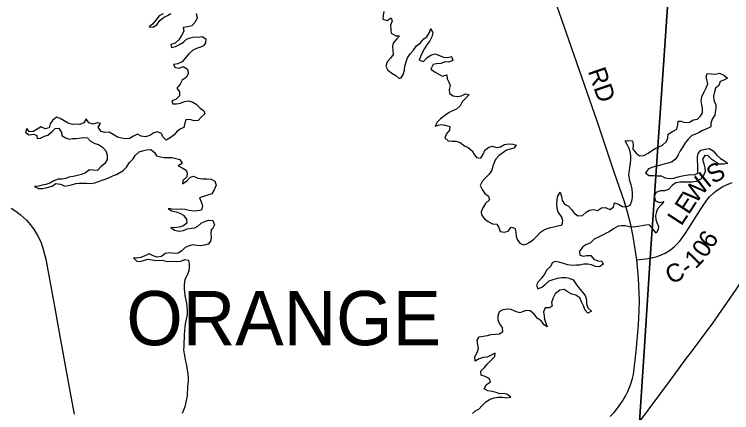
# Model space of a CAD drawing. Extents: x 1674899 to 2057726, y 653888 to 988278.
# Drawn here: x 1834248 to 1846138, y 797406 to 804014 of the extents above; entities that cross this region are included whole.
import ezdxf

# ---------------------------------------------------------------- set-up
doc = ezdxf.new("R2010")
doc.units = 0
for name, color, linetype in [('GM_X_County_Road', 7, 'Continuous'), ('GM_X_County_Road_Text', 7, 'Continuous'), ('GM_X_Interstate_Route', 7, 'Continuous'), ('GM_X_Major_Lake', 7, 'Continuous'), ('GM_X_Township', 7, 'Continuous'), ('GM_X_Township_Text', 7, 'Continuous'), ('SH_Data', 7, 'Continuous')]:
    doc.layers.add(name, color=color, linetype=linetype)

msp = doc.modelspace()

# ---------------------------------------------------------------- linework, layer by layer
at = {"layer": 'GM_X_County_Road'}
for points in [[(1844123, 797340), (1844188, 797408), (1844248, 797481), (1844329, 797598), (1844353, 797638), (1844376, 797680), (1844415, 797758), (1844451, 797843), (1844467, 797886), (1844494, 797974), (1844505, 798018), (1844519, 798085), (1844557, 798429), (1844595, 798866), (1844607, 799102), (1844608, 799265), (1844601, 799518), (1844595, 799631), (1844566, 799941), (1844505, 800330), (1844464, 800522), (1844412, 800732), (1844363, 800904), (1844193, 801395), (1843910, 802243), (1843360, 803811), (1842894, 805162)], [(1844838, 799981), (1844901, 799998), (1844968, 800023), (1845033, 800054), (1845064, 800071), (1845094, 800091), (1845124, 800110), (1845190, 800164), (1845278, 800253), (1845373, 800385), (1845425, 800462), (1845644, 800809), (1845729, 800932), (1845773, 800986), (1845847, 801059), (1845874, 801080), (1845931, 801120), (1845991, 801156), (1846052, 801187), (1846116, 801212), (1846148, 801222)], [(1834194, 800797), (1834287, 800738), (1834352, 800690), (1834449, 800601), (1834514, 800523), (1834576, 800442), (1834637, 800335), (1834686, 800241), (1834720, 800133), (1834770, 799952), (1834842, 799561), (1834917, 799142), (1834969, 798857), (1835136, 797945), (1835185, 797674), (1835238, 797383)], [(1844566, 799941), (1844753, 799964), (1844785, 799970), (1844828, 799978), (1844838, 799981)]]:
    msp.add_lwpolyline(points, dxfattribs=at)
at = {"layer": 'GM_X_Interstate_Route'}
for points in [[(1845438, 798374), (1845825, 798892), (1846211, 799449), (1846552, 799972), (1846911, 800613), (1847205, 801213), (1847493, 801891), (1847666, 802395), (1847786, 802765), (1847888, 803110), (1847964, 803419), (1848028, 803685), (1848125, 804211), (1848200, 804670), (1848231, 804991), (1848401, 807248), (1848453, 807987), (1848565, 809674), (1848656, 810925), (1848716, 811884), (1848786, 812818), (1848839, 813548), (1848865, 814059), (1848894, 814749)], [(1837487, 786429), (1837514, 786520), (1837601, 786793), (1837756, 787221), (1837932, 787687), (1838187, 788245), (1838424, 788716), (1838589, 789007), (1838800, 789367), (1839053, 789775), (1839282, 790094), (1839487, 790389), (1839554, 790475), (1839800, 790800), (1840096, 791202), (1840599, 791880), (1841473, 793063), (1842402, 794310), (1842953, 795035), (1844609, 797255), (1845106, 797922), (1845407, 798332)], [(1845407, 798332), (1845438, 798374)]]:
    msp.add_lwpolyline(points, dxfattribs=at)
at = {"layer": 'GM_X_Major_Lake'}
for points in [[(1836713, 804024), (1836647, 803990), (1836595, 803916), (1836538, 803849), (1836484, 803809), (1836544, 803799), (1836608, 803840), (1836659, 803914), (1836719, 803962), (1836787, 803993), (1836841, 804027)], [(1837261, 804027), (1837276, 803955), (1837246, 803885), (1837188, 803823), (1837122, 803807), (1837048, 803796), (1837055, 803734), (1837019, 803664), (1836972, 803594), (1836914, 803534), (1836842, 803515), (1836852, 803463), (1836918, 803482), (1836986, 803512), (1837050, 803554), (1837100, 803605), (1837164, 803627), (1837230, 803639), (1837296, 803638), (1837362, 803646), (1837422, 803608), (1837418, 803544), (1837381, 803490), (1837331, 803470), (1837267, 803448), (1837205, 803419), (1837139, 803357), (1837080, 803289), (1837028, 803224), (1836958, 803194), (1836884, 803184), (1836914, 803134), (1836978, 803124), (1837044, 803151), (1837111, 803109), (1837133, 803041), (1837098, 802969), (1837032, 802923), (1836994, 802856), (1836941, 802792), (1836985, 802730), (1836983, 802663), (1836922, 802604), (1836856, 802578), (1836874, 802528), (1836936, 802528), (1837004, 802543), (1837068, 802571), (1837138, 802577), (1837204, 802560)], [(1840372, 804063), (1840363, 804001), (1840357, 803933), (1840429, 803911), (1840493, 803957), (1840511, 803903), (1840484, 803833), (1840486, 803757), (1840495, 803703), (1840569, 803660), (1840633, 803658), (1840581, 803604), (1840528, 803534), (1840516, 803480), (1840521, 803416), (1840525, 803348), (1840485, 803288), (1840426, 803227), (1840408, 803157), (1840440, 803090), (1840505, 803038), (1840569, 802998), (1840628, 802949)], [(1840628, 802949), (1840659, 802963), (1840695, 803017), (1840715, 803087), (1840722, 803155), (1840740, 803229), (1840762, 803293), (1840809, 803361), (1840865, 803422), (1840912, 803490), (1840980, 803542), (1841036, 803607), (1841086, 803641), (1841127, 803711), (1841151, 803777), (1841187, 803705), (1841168, 803639), (1841136, 803573), (1841087, 803511), (1841047, 803445), (1841013, 803385), (1840986, 803324), (1840960, 803252), (1841028, 803231), (1841088, 803299), (1841154, 803337), (1841224, 803358), (1841294, 803334), (1841362, 803301), (1841428, 803299), (1841494, 803317), (1841515, 803249), (1841451, 803223), (1841387, 803229), (1841315, 803198), (1841241, 803194), (1841191, 803180), (1841151, 803106), (1841225, 803056), (1841282, 803022), (1841342, 802991), (1841414, 803009), (1841422, 802943), (1841449, 802889), (1841473, 802835), (1841454, 802765), (1841462, 802699), (1841524, 802662), (1841594, 802650), (1841660, 802661), (1841728, 802693), (1841788, 802683), (1841731, 802625), (1841671, 802563), (1841637, 802497), (1841576, 802440), (1841524, 802420), (1841454, 802388), (1841380, 802333), (1841314, 802283), (1841255, 802227), (1841223, 802160), (1841273, 802173), (1841323, 802185), (1841391, 802175), (1841465, 802152), (1841460, 802090), (1841408, 802028), (1841382, 801965), (1841441, 801918), (1841505, 801910), (1841571, 801911), (1841637, 801887), (1841708, 801833), (1841770, 801804), (1841838, 801752), (1841863, 801702), (1841909, 801641), (1841979, 801631), (1842017, 801695), (1842044, 801761), (1842112, 801812), (1842172, 801830), (1842238, 801806), (1842306, 801817), (1842374, 801855), (1842440, 801865), (1842508, 801862), (1842566, 801844), (1842525, 801792), (1842465, 801780), (1842405, 801763), (1842345, 801719), (1842283, 801671), (1842222, 801606), (1842178, 801502), (1842161, 801428), (1842121, 801364), (1842059, 801302), (1842002, 801243), (1841968, 801173)], [(1845303, 802243), (1845355, 802222), (1845437, 802228), (1845503, 802264), (1845569, 802275), (1845621, 802327), (1845652, 802379), (1845656, 802451), (1845642, 802511), (1845633, 802577), (1845641, 802647), (1845676, 802715), (1845716, 802793), (1845741, 802861), (1845733, 802913), (1845717, 802977), (1845732, 803033), (1845799, 803026), (1845869, 803024), (1845937, 803038), (1846007, 803007), (1846067, 802953), (1846007, 802923), (1845945, 802900), (1845926, 802836), (1845868, 802788), (1845852, 802726), (1845839, 802658)], [(1845839, 802658), (1845839, 802638), (1845849, 802576), (1845876, 802512), (1845878, 802458), (1845865, 802392), (1845859, 802342), (1845817, 802276), (1845794, 802210), (1845794, 802150), (1845724, 802114), (1845652, 802087), (1845598, 802053), (1845528, 802021), (1845477, 802004), (1845421, 801950), (1845365, 801884), (1845328, 801818), (1845286, 801751), (1845250, 801685), (1845213, 801617), (1845151, 801567), (1845085, 801548), (1845033, 801534), (1844961, 801512), (1844829, 801481), (1844761, 801453), (1844710, 801384), (1844764, 801341), (1844836, 801339), (1844908, 801334), (1844970, 801334), (1845036, 801302), (1845107, 801289), (1845177, 801295), (1845249, 801318), (1845315, 801336), (1845385, 801348), (1845449, 801357), (1845517, 801351), (1845577, 801381), (1845578, 801447), (1845576, 801515), (1845571, 801587), (1845571, 801653), (1845581, 801705), (1845626, 801759), (1845696, 801780), (1845764, 801786), (1845831, 801751), (1845887, 801683), (1845953, 801621), (1846018, 801586), (1846076, 801540), (1846008, 801528), (1845936, 801531), (1845860, 801571), (1845807, 801606), (1845751, 801668), (1845691, 801670), (1845655, 801610), (1845674, 801536), (1845692, 801470), (1845699, 801406), (1845673, 801338), (1845623, 801282), (1845551, 801243), (1845481, 801229), (1845413, 801231), (1845349, 801232), (1845281, 801228), (1845211, 801219), (1845153, 801173), (1845092, 801107), (1845024, 801084), (1844954, 801088), (1844886, 801060), (1844856, 800992), (1844875, 800922), (1844941, 800894), (1845013, 800908), (1844971, 800856), (1844914, 800794), (1844892, 800742), (1844874, 800678), (1844879, 800612), (1844897, 800562), (1844925, 800496), (1844920, 800446), (1844884, 800386), (1844832, 800458), (1844777, 800521), (1844709, 800519), (1844657, 800503), (1844585, 800492), (1844519, 800484), (1844443, 800488), (1844375, 800503), (1844307, 800503), (1844255, 800498), (1844177, 800454)], [(1837204, 802560), (1837263, 802522), (1837327, 802457), (1837389, 802413), (1837404, 802363), (1837346, 802307), (1837294, 802254), (1837228, 802250), (1837154, 802268), (1837088, 802265), (1837072, 802207), (1837057, 802139), (1837007, 802117), (1836947, 802077), (1836895, 802016), (1836831, 801966), (1836762, 801928), (1836709, 801983), (1836685, 802037), (1836623, 802067), (1836557, 802047), (1836491, 802006), (1836421, 801982), (1836351, 801993), (1836287, 802027), (1836221, 801995), (1836159, 801954), (1836093, 801948), (1836023, 801962), (1835958, 801975), (1835884, 802021), (1835820, 802058), (1835746, 802056), (1835686, 802070), (1835635, 802141), (1835677, 802202), (1835621, 802213), (1835555, 802195), (1835482, 802215), (1835440, 802280), (1835400, 802214), (1835334, 802188), (1835262, 802193), (1835210, 802189), (1835140, 802209), (1835072, 802246), (1835007, 802288), (1834947, 802306), (1834880, 802251), (1834842, 802197), (1834824, 802129), (1834760, 802117), (1834692, 802148), (1834628, 802112), (1834562, 802068), (1834500, 802065), (1834452, 802123), (1834432, 802055), (1834495, 802013), (1834569, 802024), (1834621, 802004), (1834627, 801954), (1834679, 801958), (1834749, 801993), (1834801, 802011), (1834867, 802063), (1834924, 802120), (1834984, 802124), (1835031, 802056), (1835035, 802006), (1835096, 801967), (1835162, 801943), (1835212, 801955), (1835272, 801956), (1835324, 801960), (1835388, 801972), (1835458, 801967), (1835512, 801911), (1835579, 801873), (1835641, 801856), (1835709, 801808), (1835762, 801748), (1835786, 801684), (1835785, 801607), (1835745, 801538), (1835681, 801484), (1835627, 801426), (1835555, 801427), (1835495, 801435), (1835428, 801387), (1835362, 801356), (1835292, 801338), (1835220, 801322), (1835152, 801313), (1835100, 801293), (1835036, 801279), (1834976, 801280), (1834902, 801250), (1834834, 801214), (1834768, 801193), (1834714, 801183)], [(1841968, 801173), (1842002, 801109), (1842047, 801042), (1842107, 800998), (1842126, 800936), (1842060, 800876), (1842012, 800806), (1841987, 800738), (1841989, 800686), (1842039, 800622), (1842104, 800578), (1842174, 800539), (1842246, 800535), (1842277, 800479), (1842301, 800414), (1842367, 800398), (1842435, 800418), (1842481, 800483), (1842543, 800467), (1842559, 800399), (1842568, 800333), (1842580, 800281), (1842625, 800220), (1842689, 800188), (1842741, 800208), (1842791, 800234), (1842858, 800287), (1842910, 800335), (1842970, 800399), (1843020, 800434), (1843080, 800460), (1843142, 800476), (1843192, 800491), (1843256, 800507), (1843329, 800525), (1843341, 800595), (1843319, 800663), (1843264, 800731), (1843248, 800791), (1843241, 800859), (1843245, 800935), (1843256, 800997), (1843296, 801063), (1843317, 800993), (1843331, 800927), (1843369, 800863), (1843436, 800832), (1843482, 800774), (1843531, 800712), (1843593, 800673), (1843667, 800679), (1843727, 800733), (1843782, 800768), (1843850, 800774), (1843915, 800762), (1843982, 800807), (1844048, 800809), (1844117, 800778), (1844181, 800818), (1844196, 800890), (1844260, 800864), (1844327, 800829), (1844391, 800821), (1844457, 800849), (1844484, 800914), (1844492, 800980), (1844496, 801042), (1844491, 801117), (1844473, 801185), (1844456, 801235), (1844444, 801285), (1844435, 801359), (1844443, 801425), (1844449, 801479), (1844460, 801541), (1844468, 801605), (1844468, 801671), (1844453, 801735), (1844437, 801789), (1844408, 801855), (1844370, 801918), (1844424, 801921), (1844492, 801915), (1844506, 801849), (1844501, 801777), (1844553, 801709), (1844612, 801668), (1844684, 801670), (1844754, 801711), (1844827, 801759), (1844879, 801793), (1844929, 801819), (1844993, 801846), (1845055, 801906), (1845080, 801958), (1845088, 802026), (1845158, 802071), (1845228, 802111), (1845245, 802179), (1845251, 802243), (1845303, 802243)], [(1834714, 801183), (1834646, 801163), (1834580, 801156), (1834648, 801127), (1834716, 801127), (1834792, 801139), (1834872, 801162), (1834934, 801208), (1835010, 801197), (1835089, 801165), (1835139, 801177), (1835194, 801188), (1835268, 801208), (1835320, 801212), (1835445, 801211), (1835509, 801207), (1835579, 801220), (1835705, 801262), (1835755, 801281), (1835824, 801307), (1835892, 801339), (1835942, 801360), (1835994, 801388), (1836050, 801422), (1836106, 801478), (1836159, 801557), (1836219, 801619), (1836251, 801673), (1836316, 801731), (1836374, 801752), (1836440, 801764), (1836508, 801770), (1836569, 801725), (1836603, 801665), (1836669, 801649), (1836733, 801642), (1836805, 801640), (1836856, 801638), (1836922, 801621), (1836988, 801607), (1837028, 801541), (1836961, 801501), (1837029, 801468), (1837093, 801430), (1837115, 801380), (1837104, 801318), (1837040, 801256), (1837036, 801204), (1837104, 801252), (1837168, 801314), (1837218, 801327), (1837290, 801295), (1837366, 801285), (1837438, 801284), (1837510, 801282), (1837571, 801247), (1837591, 801181), (1837560, 801103), (1837520, 801036), (1837448, 801014), (1837382, 800994), (1837316, 800971), (1837345, 800902), (1837365, 800838), (1837351, 800768), (1837283, 800755), (1837215, 800751), (1837145, 800761), (1837079, 800776), (1837009, 800782), (1836937, 800777), (1836865, 800781), (1836799, 800791), (1836853, 800755), (1836931, 800739), (1836989, 800718), (1837054, 800680), (1837102, 800612), (1837109, 800552), (1837041, 800498), (1836979, 800484), (1836909, 800475), (1836841, 800477), (1836905, 800433), (1836979, 800418), (1837049, 800430), (1837115, 800455), (1837185, 800469), (1837237, 800475), (1837289, 800502), (1837345, 800548), (1837417, 800584), (1837469, 800600), (1837537, 800593), (1837567, 800521), (1837532, 800455)], [(1837532, 800455), (1837512, 800437), (1837504, 800377), (1837510, 800313), (1837501, 800251), (1837461, 800199), (1837397, 800184), (1837335, 800172), (1837273, 800180), (1837205, 800189), (1837143, 800175), (1837077, 800147), (1837023, 800090), (1836961, 800052), (1836889, 800046), (1836819, 800057), (1836749, 800045), (1836687, 799999), (1836613, 799986), (1836549, 800010), (1836481, 800041), (1836413, 800007), (1836345, 799983), (1836277, 799970), (1836221, 799974), (1836280, 799922), (1836334, 799915), (1836404, 799935), (1836468, 799951), (1836532, 799942), (1836594, 799932), (1836648, 799934), (1836718, 799931), (1836786, 799915), (1836864, 799922), (1836928, 799914), (1837006, 799922), (1837072, 799949), (1837132, 799937), (1837143, 799871), (1837145, 799819), (1837141, 799759), (1837112, 799687), (1837076, 799617), (1837063, 799531), (1837061, 799465), (1837066, 799407), (1837076, 799351), (1837103, 799215), (1837107, 799165), (1837115, 799113), (1837110, 799033), (1837102, 798979), (1837085, 798905), (1837073, 798831), (1837066, 798765), (1837062, 798711), (1837062, 798639), (1837059, 798574), (1837057, 798500), (1837053, 798450), (1837064, 798380), (1837076, 798322), (1837087, 798254), (1837099, 798188), (1837114, 798114), (1837124, 798050), (1837128, 797976), (1837127, 797924), (1837117, 797848), (1837116, 797792), (1837114, 797740), (1837110, 797686), (1837103, 797634), (1837091, 797578), (1837071, 797504), (1837052, 797450), (1837032, 797394)], [(1844177, 800454), (1844109, 800404), (1844059, 800383), (1843995, 800351), (1843931, 800319), (1843860, 800284), (1843792, 800220), (1843720, 800188), (1843670, 800157), (1843613, 800087), (1843621, 800019), (1843683, 800000), (1843733, 800014), (1843803, 800014), (1843852, 799953), (1843920, 799927), (1843988, 799919), (1844006, 799869), (1843945, 799823), (1843880, 799833), (1843812, 799856), (1843752, 799868), (1843690, 799868), (1843622, 799855), (1843564, 799851), (1843494, 799849), (1843422, 799858), (1843349, 799882), (1843279, 799901), (1843211, 799915), (1843161, 799891), (1843138, 799835), (1843074, 799778), (1843034, 799704), (1842983, 799640), (1842931, 799574), (1842903, 799523), (1842924, 799460), (1842994, 799490), (1843047, 799534), (1843115, 799595), (1843177, 799617), (1843249, 799637), (1843319, 799650), (1843393, 799650), (1843445, 799636), (1843513, 799609), (1843554, 799543), (1843602, 799477), (1843659, 799410), (1843709, 799348), (1843734, 799278), (1843734, 799212), (1843755, 799146), (1843817, 799089), (1843751, 799057), (1843707, 799108), (1843680, 799178), (1843650, 799246), (1843619, 799312), (1843555, 799355), (1843491, 799371), (1843427, 799404), (1843364, 799452), (1843292, 799438), (1843211, 799375), (1843181, 799309), (1843151, 799235), (1843162, 799171), (1843112, 799143), (1843044, 799145), (1843018, 799080), (1843031, 799009), (1843035, 798957), (1843059, 798893), (1843080, 798833), (1843029, 798863), (1842979, 798928), (1842915, 798976), (1842862, 799038), (1842800, 799095), (1842730, 799103), (1842666, 799080)], [(1841841, 797393), (1841895, 797441), (1841947, 797467), (1842001, 797526), (1842062, 797584), (1842134, 797630), (1842202, 797653), (1842268, 797663), (1842340, 797661), (1842406, 797652), (1842476, 797666), (1842410, 797712), (1842346, 797723), (1842294, 797721), (1842234, 797741), (1842167, 797760), (1842097, 797766), (1842037, 797804), (1842073, 797874), (1842140, 797918), (1842116, 797974), (1842052, 798004), (1841988, 798031), (1841981, 798095), (1842039, 798153), (1842092, 798218), (1842150, 798280), (1842212, 798340), (1842216, 798392), (1842150, 798358), (1842084, 798326), (1842018, 798321), (1841950, 798297), (1841886, 798263), (1841882, 798332), (1841921, 798403), (1841941, 798469), (1841930, 798533), (1841918, 798607), (1841954, 798665), (1842020, 798673), (1842088, 798689), (1842154, 798704), (1842222, 798706), (1842290, 798713), (1842345, 798755), (1842341, 798817), (1842287, 798884), (1842270, 798948), (1842266, 799012), (1842289, 799084), (1842349, 799117), (1842417, 799127), (1842479, 799123), (1842548, 799090), (1842622, 799070), (1842666, 799080)]]:
    msp.add_lwpolyline(points, dxfattribs=at)
at = {"layer": 'GM_X_Township'}
for points in [[(1826634, 806376), (1831742, 806059), (1832763, 805986), (1837716, 805633), (1840812, 805456), (1842837, 805328), (1843041, 805313), (1843103, 805315), (1843287, 805303), (1845145, 805182), (1844785, 799970), (1844685, 798421), (1844609, 797255), (1844527, 794924), (1844507, 794629), (1844500, 794432), (1844479, 794298), (1844463, 793924), (1844418, 793241), (1844305, 791617), (1844278, 791160), (1843918, 786568)], [(1843918, 786568), (1844278, 791160), (1844305, 791617), (1844418, 793241), (1844463, 793924), (1844479, 794298), (1844500, 794432), (1844507, 794629), (1844527, 794924), (1844609, 797255), (1844685, 798421), (1844785, 799970), (1845145, 805182), (1848231, 804991), (1849953, 804892), (1851286, 804810), (1852898, 804710), (1852972, 804706), (1853920, 804647), (1855314, 804559), (1855512, 804546)]]:
    msp.add_lwpolyline(points, dxfattribs=at)
at = {"layer": 'SH_Data'}
for points in [[(1845438, 798374), (1845825, 798892), (1846211, 799449), (1846552, 799972), (1846911, 800613), (1847205, 801213), (1847493, 801891), (1847666, 802395), (1847786, 802765), (1847888, 803110), (1847964, 803419), (1848028, 803685), (1848125, 804211), (1848200, 804670), (1848231, 804991), (1848401, 807248), (1848453, 807987), (1848565, 809674), (1848656, 810925), (1848716, 811884), (1848786, 812818), (1848839, 813548), (1848865, 814059), (1848894, 814749)], [(1837487, 786429), (1837514, 786520), (1837601, 786793), (1837756, 787221), (1837932, 787687), (1838187, 788245), (1838424, 788716), (1838589, 789007), (1838800, 789367), (1839053, 789775), (1839282, 790094), (1839487, 790389), (1839554, 790475), (1839800, 790800), (1840096, 791202), (1840599, 791880), (1841473, 793063), (1842402, 794310), (1842953, 795035), (1844609, 797255), (1845106, 797922), (1845407, 798332)], [(1845407, 798332), (1845438, 798374)]]:
    msp.add_lwpolyline(points, dxfattribs=at)

# ---------------------------------------------------------------- texts
at = {"layer": 'GM_X_County_Road_Text'}
for s, rotation, p in [('RD', 289.0585, (1843751, 803073)), ('S', 29.9329, (1845830, 801194)), ('I', 39.2389, (1845745, 801123)), ('W', 52.0311, (1845543, 800861)), ('E', 56.9625, (1845425, 800679)), ('L', 56.9874, (1845303, 800491)), ('6', 56.2746, (1845810, 800112)), ('0', 55.9139, (1845705, 799957)), ('1', 45.9473, (1845541, 799780)), ('C', 25.7516, (1845129, 799529)), ('-', 38.2082, (1845411, 799674))]:
    msp.add_text(s, height=300, rotation=rotation, dxfattribs=at).set_placement(p)
at = {"layer": 'GM_X_Township_Text'}
msp.add_text('ORANGE', height=900, rotation=0, dxfattribs=at).set_placement((1836104, 798525))

doc.saveas('drawing.dxf')
